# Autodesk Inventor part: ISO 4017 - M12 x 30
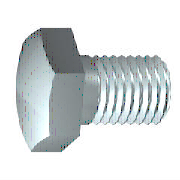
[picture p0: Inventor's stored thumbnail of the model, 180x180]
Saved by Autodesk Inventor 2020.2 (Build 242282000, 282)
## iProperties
Manager: www.cadconsulting.pl
Company: Fabian Stasiak CAD Consulting
Created: 2010-02
Part Number: ISO 4017 - M12 x 30
Material: Stal, miękka
Description: Śruba z łbem sześciokątnym
Document SubType Name: Modeling
Standard: DIN EN 24 017
Designer: F.Stasiak
Standards Organization: DIN
Language: pl-PL
Size Designation: M12 x 30
Categories: <MemberInstance><Categories><Category DisplayName="Mocowania" InternalName="e4da775c-781d-43d5-af7c-5136215cf5a6" Mnemonic="FSTN"><Category DisplayName="Śruby"
Density: 1 g/cm^3
Appearance: Stal
IsCustomPart: 0
Author: F.Stasiak
Subject: Zbiór ćwiczeń. Autodesk Inventor 2020. Kurs podstawowy
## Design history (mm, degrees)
sketch "Sketch1"
  geometry: L1 (0, 8.315)-(0, 6); L2 (5.3, 6)-(30, 6); L3 (30, 6)-(30, 0); L4 (30, 0)-(-0.6, 0); L5 (-6.72, 0)-(36.12, 0) reference; L6 (-0.6, 0)-(-0.6, 8.315); L7 (-0.6, 8.315)-(0, 8.315); L8 (5.3, 6)-(4.226, 6); L9 (4.226, 6)-(0, 6); L10 (0, -1.663)-(0, 9.978) reference
  constraints: 16 end point, 2 collinear, 2 perpendicular, 1 parallel
  dimensions: "d0" = 30 distance between parallel lines of L3 L1 (= NLG); "d1" = 24.7 distance from line of L2.start L3 (= GEL); "d2" = 12 diameter of L2 L4 (= GD); "d9" = 0.6001 distance between parallel lines of L6 L1 (computed from SD); "d10" = 16.63 diameter of L7 L4 (= SD2); "d13" = 1.07364 distance of L2.start L8.end (computed from GAL); "d14" = 12 diameter of L9 L4 (= BDM)
revolve "Body" sketch "Sketch1" stored, may be unused: angle "d12" = 90 deg
sketch "Sketch2"
  geometry: L1 (0, 10.392)-(9, 5.196); L2 (9, 5.196)-(9, -5.196); L3 (9, -5.196)-(0, -10.392); L4 (0, -10.392)-(-9, -5.196); L5 (-9, -5.196)-(-9, 5.196); L6 (-9, 5.196)-(0, 10.392); 2 further points
  constraints: 12 end point, 1 coincident, 1 vertical, 11 other
  dimensions: "d11" = 18 distance between parallel lines of L5 L2 (= SW)
extrude "Head" join sketch "Sketch2" distance "d3" = 6.9 (= KOH - SD); taper "d4" = 0 deg
sketch "Sketch4"
  geometry: L1 (-7.5, 9)-(-7.5, 10.392); L2 (-7.5, 10.392)-(-6.696, 10.392); L3 (-6.696, 10.392)-(-7.5, 9); L4 (-8.88, 0)-(0.78, 0) reference; L5 (-0.6, 10.392)-(-7.5, 10.392) reference; L6 (-7.5, 5.196)-(-7.5, 10.392) reference
  constraints: 6 end point, 2 collinear, 1 perpendicular, 1 vertical
  dimensions: "d5" = 30 deg angle of L3 L1 (= ANG1); "d19" = 18 diameter of L1.start L4 (= SW0)
revolve "Chamfer1" sketch "Sketch4" stored, may be unused: angle "d21" = 90 deg
feature "Thread" dims "d15" = 24.7 (= GEL), "d16" = 0
chamfer "Chamfer2" distance "d6" = 1.07354 (= -0.5 x SPD + 0.5 x GD); stored, may be unused: second distance "d7" = 1.07364 (computed from GUL), angle "d55" = 45 deg
workplane "Work Plane1"
body "Solid1"
other parameters: "NLG" = 30 [user parameter; used in 1 equation term], "GD" = 12 (= NND) [user parameter; used in 2 equation terms], "BDM" = 12 (= NND) [user parameter; used in 1 equation term], "KOH" = 7.5 [user parameter; used in 1 equation term], "GEL" = 24.7 [user parameter; used in 2 equation terms], "SW" = 18 [user parameter; used in 2 equation terms], "SW0" = 18 (= SW) [user parameter; used in 1 equation term], "SPD" = 9.85293 (= NND - 1.2269 x PTC) [user parameter; used in 1 equation term], "SD2" = 16.63 [user parameter; used in 2 equation terms], "SD" = 0.6 [user parameter; used in 2 equation terms], "ANG1" = 30 deg [user parameter; used in 1 equation term], "GAL" = 1.07354 (= 0.61345 x PTC) [user parameter; used in 1 equation term], "GUL" = 1.07354 (= 0.61345 x PTC) [user parameter; used in 1 equation term], "d8" = 0, "RR" = 0.6 [user parameter], "d57" = 0, "d58" = 0, "TPU" = 5.71429 (computed from PTC) [user parameter], "GD1" = 9.85293 (= THREADDIA - 1.2269 x PTC) [user parameter], "THREADDIA" = 12 [user parameter; used in 1 equation term], "SDH" = 16.63 (= SD2) [user parameter], "SDHG" = 5.3 [user parameter], "TOA" = 30 deg [user parameter], "PTC" = 1.75 [user parameter; used in 5 equation terms], "NND" = 12 [user parameter; used in 3 equation terms], "E0" = 20.79 [user parameter]
